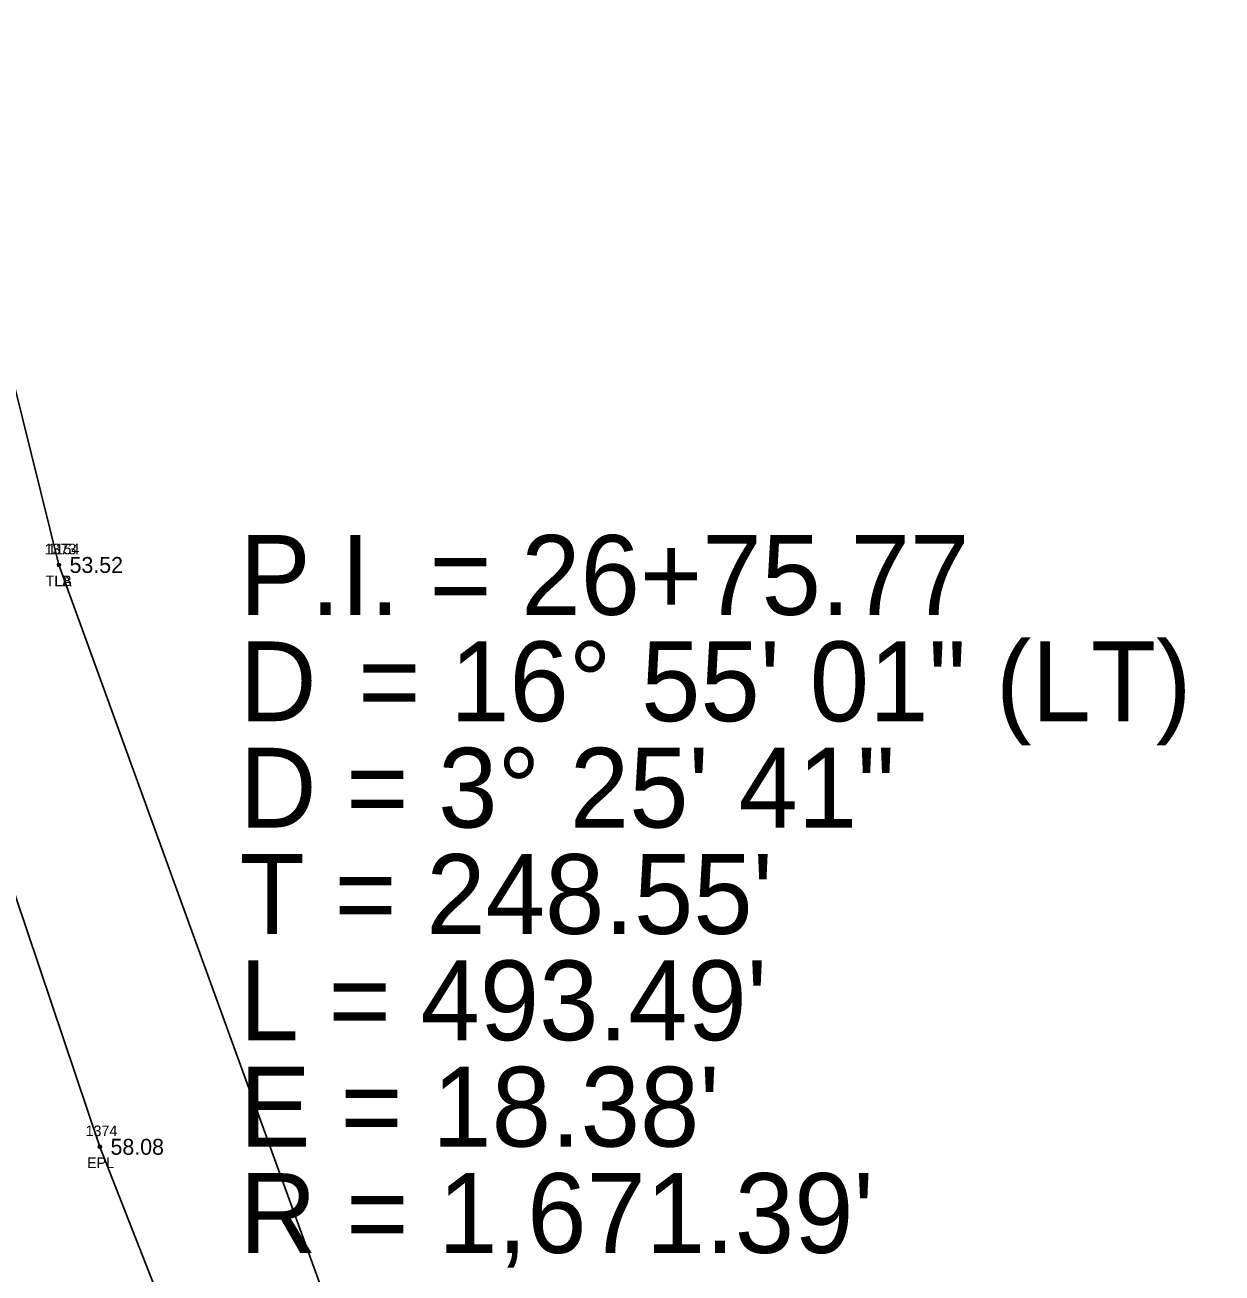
# Model space of a CAD drawing. Extents: x 2396531 to 2397633, y 770203 to 772837.
# Drawn here: x 2397123.8 to 2397236.4, y 771166.1 to 771283.5 of the extents above; entities that cross this region are included whole.
import ezdxf

# ---------------------------------------------------------------- set-up
doc = ezdxf.new("R2010")
doc.units = 0
for name, color, linetype in [('RD_EX_Road', 7, 'Continuous'), ('RD_EX_Road_txCode', 7, 'Continuous'), ('RD_EX_TX_Road_ELEV', 7, 'Continuous'), ('RD_EX_TX_VEG_ELEV', 7, 'Continuous'), ('RD_EX_VEG', 7, 'Continuous'), ('RD_EX_VEG_txCode', 7, 'Continuous'), ('RD_HC_Cl', 7, 'Continuous'), ('RD_HC_Data', 7, 'Continuous'), ('RD_SMD_Locator', 7, 'Continuous')]:
    doc.layers.add(name, color=color, linetype=linetype)

msp = doc.modelspace()

# ---------------------------------------------------------------- linework, layer by layer
at = {"layer": 'RD_EX_Road'}
msp.add_lwpolyline([(2397113.76, 771228.75), (2397130.87, 771177.98), (2397154.19, 771118.49), (2397170.38, 771081.25), (2397178.53, 771063.49), (2397207.96, 771004.56), (2397238.54, 770949.11), (2397245.72, 770936.59), (2397280.76, 770876.73)], dxfattribs=at)
at = {"layer": 'RD_EX_VEG'}
msp.add_lwpolyline([(2397137.17, 771710.16), (2397010.6, 771680.28), (2397078.29, 771429.37), (2397127.02, 771232.69), (2397127.02, 771232.69), (2397166.52, 771123.83), (2397178.02, 771098.29), (2397254.06, 771102.5)], dxfattribs=at)
at = {"layer": 'RD_HC_Cl'}
msp.add_arc((2398682.18, 771766.08), 1671.39, 194.59125, 211.50817, dxfattribs=at)
at = {"layer": 'RD_SMD_Locator'}
for centre in [(2397127.02, 771232.69), (2397127.02, 771232.69), (2397130.87, 771177.98)]:
    msp.add_circle(centre, 0.15, dxfattribs=at)

# ---------------------------------------------------------------- texts
at = {"layer": 'RD_EX_Road_txCode'}
for s, p in [('1374', (2397129.53, 771178.98)), ('EPL', (2397129.67, 771175.98))]:
    msp.add_text(s, height=1, dxfattribs=at).set_placement(p)
at = {"layer": 'RD_EX_TX_Road_ELEV'}
msp.add_text('58.08', height=1.5, dxfattribs=at).set_placement((2397131.87, 771177.23))
at = {"layer": 'RD_EX_TX_VEG_ELEV'}
msp.add_text('53.52', height=1.5, dxfattribs=at).set_placement((2397128.02, 771231.94))
msp.add_text('53.52', height=1.5, dxfattribs=at).set_placement((2397128.02, 771231.94))
at = {"layer": 'RD_EX_VEG_txCode'}
for s, p in [('1373', (2397125.68, 771233.69)), ('1154', (2397125.96, 771233.69)), ('TLA', (2397125.76, 771230.69)), ('TLB', (2397125.78, 771230.69))]:
    msp.add_text(s, height=1, dxfattribs=at).set_placement(p)
at = {"layer": 'RD_HC_Data'}
for s, p in [('P.I. = 26+75.77', (2397144, 771228)), ('    = 16%%d 55\' 01" (LT)', (2397144, 771218)), ('D', (2397144, 771218)), ('D = 3%%d 25\' 41"', (2397144, 771208)), ("T = 248.55'", (2397144, 771198)), ("L = 493.49'", (2397144, 771188)), ("E = 18.38'", (2397144, 771178)), ("R = 1,671.39'", (2397144, 771168))]:
    msp.add_text(s, height=7.5, dxfattribs=at).set_placement(p)

doc.saveas('drawing.dxf')
